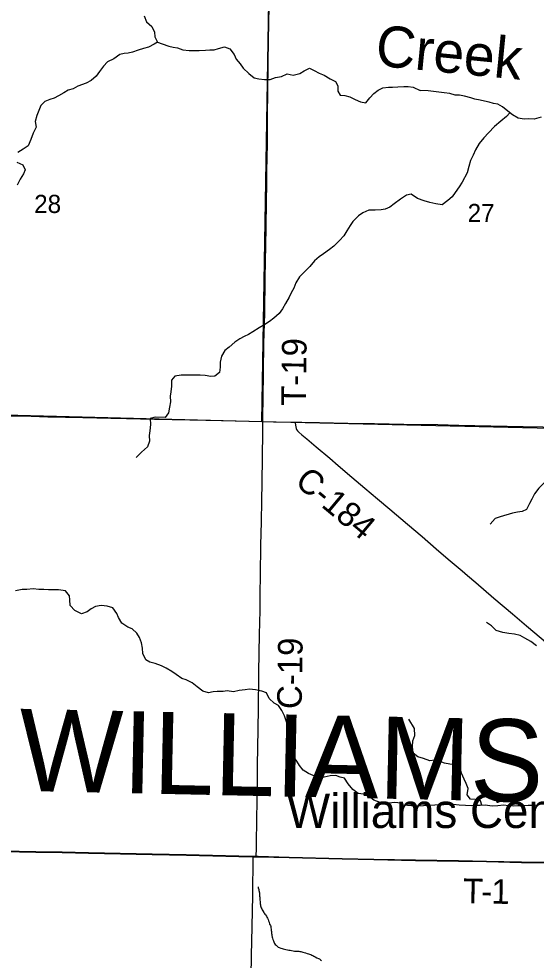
# Model space of a CAD drawing. Extents: x 0 to 34, y 0 to 22.
# Drawn here: x 3.097 to 4.291, y 16.256 to 18.428 of the extents above; entities that cross this region are included whole.
import ezdxf

# ---------------------------------------------------------------- set-up
doc = ezdxf.new("R2010")
doc.units = 0
for name, color, linetype in [('GM_X_County_Road', 7, 'Continuous'), ('GM_X_County_Road_Text', 7, 'Continuous'), ('GM_X_County_Text', 7, 'Continuous'), ('GM_X_Minor_River', 7, 'Continuous'), ('GM_X_Minor_River_Text', 7, 'Continuous'), ('GM_X_Section', 7, 'Continuous'), ('GM_X_Section_Text', 7, 'Continuous'), ('GM_X_Township_Road', 7, 'Continuous'), ('GM_X_Township_Road_Text', 7, 'Continuous'), ('GM_X_Unincorporated_Text', 7, 'Continuous'), ('GM_X_US_Route', 7, 'Continuous'), ('SH_Cut_Line', 7, 'Continuous')]:
    doc.layers.add(name, color=color, linetype=linetype)

msp = doc.modelspace()

# ---------------------------------------------------------------- linework, layer by layer
at = {"layer": 'GM_X_County_Road'}
msp.add_line((3.6378, 16.4946), (3.6451, 16.4944), dxfattribs=at)
for points in [[(3.6601, 17.499), (3.6602, 17.5105), (3.6605, 17.5528), (3.6615, 17.6119), (3.6626, 17.6796), (3.6643, 17.748), (3.6655, 17.8307), (3.6667, 17.9059), (3.6674, 17.9469), (3.6685, 18.0066), (3.669, 18.0464), (3.6695, 18.0806), (3.6699, 18.1042), (3.6705, 18.1427), (3.6711, 18.1831), (3.6712, 18.2148), (3.6714, 18.249), (3.6717, 18.2701), (3.6722, 18.3105), (3.6727, 18.3397), (3.6735, 18.3901), (3.6741, 18.4261), (3.6746, 18.4498)], [(3.6451, 16.4944), (3.6449, 16.4976), (3.6449, 16.5014), (3.6451, 16.5082), (3.6453, 16.5281), (3.6468, 16.6263), (3.6475, 16.6691), (3.648, 16.7015), (3.6486, 16.7512), (3.6489, 16.7841), (3.6499, 16.8419), (3.6503, 16.8655), (3.6505, 16.8836), (3.6509, 16.9184), (3.6518, 16.9668), (3.6525, 17.006), (3.6531, 17.0364), (3.6536, 17.0613), (3.6542, 17.1011), (3.6549, 17.144), (3.6558, 17.2136), (3.6568, 17.267), (3.6576, 17.3167), (3.6582, 17.3571), (3.6601, 17.4752), (3.6601, 17.499)], [(3.7344, 17.4974), (3.7347, 17.4953), (3.7359, 17.4864), (3.7368, 17.4826), (3.7379, 17.4802), (3.7397, 17.4776), (3.7432, 17.4739), (3.7504, 17.4678), (3.7615, 17.4587), (3.7828, 17.4406), (3.8148, 17.4139), (3.8341, 17.3973), (3.8654, 17.3708), (3.8953, 17.3454), (3.9249, 17.3208), (3.9532, 17.2965), (3.9939, 17.2618), (4.0275, 17.2332), (4.0601, 17.2053), (4.088, 17.1815), (4.1202, 17.1541), (4.1324, 17.1436), (4.1518, 17.127), (4.1934, 17.0915), (4.2364, 17.0547), (4.2685, 17.0272), (4.2876, 17.0113), (4.3472, 16.9614)], [(2.6448, 16.5144), (2.8005, 16.5116), (2.9068, 16.5095), (2.9572, 16.5086), (3.0604, 16.5067), (3.1362, 16.5053), (3.1971, 16.5041), (3.2581, 16.5028), (3.4047, 16.4997), (3.4837, 16.498), (3.6049, 16.4953), (3.6286, 16.4947), (3.6378, 16.4946)]]:
    msp.add_lwpolyline(points, dxfattribs=at)
at = {"layer": 'GM_X_County_Text'}
for points in [[(3.0601, 16.5072), (3.136, 16.5059), (3.1969, 16.5047), (3.2578, 16.5034), (3.4045, 16.5002), (3.4834, 16.4986), (3.6047, 16.4958), (3.6284, 16.4952), (3.6376, 16.4952), (3.6449, 16.495), (3.6492, 16.4949), (3.721, 16.493), (3.8428, 16.49), (3.9161, 16.4884), (4.0125, 16.4864), (4.1113, 16.4848), (4.1766, 16.4837), (4.2567, 16.4818), (4.3239, 16.4808)], [(4.3239, 16.4808), (4.2567, 16.4818), (4.1766, 16.4837), (4.1113, 16.4848), (4.0125, 16.4864), (3.9161, 16.4884), (3.8428, 16.49), (3.721, 16.493), (3.6492, 16.4949), (3.6449, 16.495), (3.6376, 16.4952), (3.6284, 16.4952), (3.6047, 16.4958), (3.4834, 16.4986), (3.4045, 16.5002), (3.2578, 16.5034), (3.1969, 16.5047), (3.136, 16.5059), (3.0601, 16.5072)]]:
    msp.add_lwpolyline(points, dxfattribs=at)
at = {"layer": 'GM_X_Minor_River'}
for points in [[(3.3862, 18.4354), (3.3919, 18.4216), (3.4042, 18.4103), (3.4103, 18.3972), (3.4108, 18.3866), (3.4173, 18.3746), (3.4274, 18.3702), (3.4432, 18.3652), (3.4531, 18.3631), (3.4633, 18.3613), (3.4753, 18.3564), (3.4897, 18.3549), (3.5018, 18.355), (3.5128, 18.3547), (3.5276, 18.3558), (3.5379, 18.3563), (3.5474, 18.3568), (3.5577, 18.3596), (3.5715, 18.3634), (3.5839, 18.3589), (3.5938, 18.3458), (3.5988, 18.335), (3.608, 18.3241), (3.615, 18.3141), (3.6276, 18.302), (3.6399, 18.2918), (3.6508, 18.2896), (3.6637, 18.2882), (3.6766, 18.2882), (3.6896, 18.2928), (3.7029, 18.2951), (3.716, 18.3009), (3.73, 18.2982), (3.7456, 18.302), (3.7553, 18.3078), (3.7676, 18.3143), (3.7788, 18.3087), (3.7897, 18.3031), (3.8017, 18.2979), (3.8155, 18.2899), (3.8275, 18.2836), (3.8329, 18.2735), (3.833, 18.2614), (3.8388, 18.2518), (3.8494, 18.2511), (3.8607, 18.2478), (3.8731, 18.2418), (3.8851, 18.2365), (3.8976, 18.2343), (3.9066, 18.2458), (3.916, 18.2555), (3.9264, 18.2632), (3.9368, 18.2693), (3.9501, 18.2701), (3.9596, 18.2707), (3.9718, 18.2711), (3.9851, 18.2719), (3.9953, 18.272), (4.0071, 18.2702), (4.0228, 18.2628)], [(3.4173, 18.3746), (3.4092, 18.3695), (3.3961, 18.363), (3.385, 18.3599), (3.372, 18.3557), (3.359, 18.3511), (3.3495, 18.3491), (3.34, 18.3482), (3.3297, 18.3461), (3.3161, 18.3359), (3.3019, 18.3286), (3.2922, 18.319), (3.2831, 18.3064), (3.2752, 18.2959), (3.264, 18.2856), (3.2521, 18.2794), (3.2329, 18.2731), (3.2221, 18.2669), (3.2107, 18.2638), (3.2006, 18.2576), (3.1883, 18.2503), (3.1783, 18.2453), (3.1684, 18.2418), (3.1569, 18.2375), (3.1475, 18.2279), (3.1434, 18.217), (3.1382, 18.205), (3.1348, 18.1914), (3.1371, 18.178), (3.1303, 18.1642), (3.1243, 18.1499), (3.1186, 18.1352), (3.107, 18.1272), (3.095, 18.1199)], [(4.1715, 18.2381), (4.1617, 18.2406), (4.1496, 18.2431), (4.1398, 18.2456), (4.1254, 18.25), (4.1141, 18.2518), (4.1039, 18.2523), (4.0918, 18.2556), (4.0786, 18.2574), (4.0664, 18.2587), (4.0536, 18.2601), (4.0415, 18.2619), (4.0228, 18.2628)], [(4.3023, 18.2011), (4.2859, 18.1968), (4.2727, 18.1971), (4.2632, 18.1969), (4.2496, 18.1991), (4.2361, 18.2069), (4.2252, 18.2151), (4.2129, 18.2248), (4.202, 18.2311), (4.1922, 18.2328), (4.182, 18.2356), (4.1715, 18.2381)], [(4.2303, 18.2113), (4.2227, 18.2026), (4.2093, 18.1923), (4.195, 18.1796), (4.181, 18.1647), (4.1698, 18.1539), (4.1593, 18.1401), (4.1511, 18.1258), (4.1452, 18.1138), (4.1392, 18.101), (4.1356, 18.0875), (4.1315, 18.0727), (4.1201, 18.051), (4.1134, 18.0401), (4.1041, 18.0274), (4.0967, 18.0176), (4.0867, 18.0091), (4.0736, 17.9991), (4.0592, 18.0009), (4.0452, 18.0046), (4.0324, 18.0083), (4.0169, 18.0137)], [(3.0926, 18.0972), (3.1061, 18.0912), (3.1119, 18.08), (3.1078, 18.0702), (3.0999, 18.0579), (3.0931, 18.044)], [(4.0169, 18.0137), (4.0027, 18.0232), (3.9916, 18.0216), (3.9781, 18.0117), (3.9634, 18.0011), (3.9529, 17.9934), (3.9426, 17.9891), (3.933, 17.9874), (3.9194, 17.9866), (3.9049, 17.9863), (3.8911, 17.9805), (3.8811, 17.9736), (3.8678, 17.9606), (3.8619, 17.9509), (3.854, 17.9386), (3.8473, 17.927), (3.8371, 17.9163), (3.8239, 17.9033), (3.8142, 17.8956), (3.7999, 17.8857), (3.7899, 17.8792), (3.7794, 17.8699), (3.7688, 17.8569), (3.7563, 17.8444), (3.7447, 17.8329), (3.7363, 17.8187), (3.7318, 17.8067), (3.7251, 17.7955), (3.7211, 17.7857), (3.7127, 17.7715), (3.7056, 17.7592), (3.6977, 17.7484), (3.6857, 17.7373), (3.6756, 17.7296), (3.6648, 17.7226), (3.6517, 17.715), (3.637, 17.7055), (3.627, 17.6997), (3.6167, 17.695), (3.6067, 17.6896), (3.5955, 17.6823), (3.5823, 17.6701), (3.5726, 17.6624), (3.5643, 17.6494), (3.5617, 17.6361), (3.5614, 17.6244), (3.5603, 17.6119), (3.5494, 17.6035), (3.5399, 17.6026), (3.5267, 17.6048), (3.5157, 17.6055), (3.5013, 17.6055), (3.4907, 17.6057), (3.4812, 17.6056), (3.4713, 17.6055), (3.4568, 17.6039), (3.449, 17.5943), (3.449, 17.5806), (3.4476, 17.5674), (3.4462, 17.5576), (3.4466, 17.5446), (3.4448, 17.5318), (3.4425, 17.519), (3.4343, 17.5085), (3.4112, 17.5091), (3.4004, 17.5056), (3.4005, 17.4923), (3.3993, 17.4776), (3.3979, 17.4666), (3.3984, 17.4537), (3.3942, 17.4401), (3.3802, 17.428), (3.3678, 17.4158)], [(4.3439, 17.3705), (4.334, 17.3688), (4.3238, 17.3671), (4.3103, 17.3578), (4.2968, 17.3452), (4.2867, 17.3321), (4.2808, 17.3194), (4.2753, 17.3096), (4.2682, 17.2961), (4.2582, 17.2914), (4.248, 17.2897), (4.2365, 17.2872), (4.2076, 17.2787), (4.1961, 17.2747), (4.1848, 17.2617)], [(3.9839, 16.6138), (3.9782, 16.6178), (3.965, 16.62), (3.9444, 16.6175), (3.9308, 16.6197), (3.9165, 16.6247), (3.9065, 16.6329), (3.8922, 16.6386), (3.8797, 16.6404), (3.8678, 16.6498), (3.8571, 16.6626), (3.8487, 16.6757), (3.8389, 16.6783), (3.8288, 16.6816), (3.8151, 16.6808), (3.8014, 16.6781), (3.7899, 16.6769), (3.776, 16.6818), (3.7651, 16.6866), (3.7532, 16.6945), (3.7444, 16.7054), (3.7385, 16.715), (3.729, 16.7278), (3.724, 16.7408), (3.7247, 16.7529), (3.7262, 16.7658), (3.7238, 16.7753), (3.7185, 16.7929), (3.7147, 16.8059), (3.7101, 16.8193), (3.7039, 16.8316), (3.6959, 16.8432), (3.6862, 16.8488), (3.6747, 16.8597), (3.6682, 16.8724), (3.6577, 16.8768), (3.6433, 16.8795), (3.6293, 16.881), (3.6194, 16.8797), (3.6057, 16.8778), (3.5927, 16.8747), (3.578, 16.8777), (3.5684, 16.8761), (3.5548, 16.8757), (3.5453, 16.8748), (3.5346, 16.8728), (3.5214, 16.8765), (3.5087, 16.8864), (3.4969, 16.8961), (3.483, 16.9026), (3.4732, 16.9059), (3.4598, 16.9149), (3.4497, 16.9216), (3.4366, 16.9296), (3.4261, 16.9352), (3.4118, 16.9405), (3.3994, 16.9438), (3.3897, 16.9486), (3.3832, 16.9632), (3.382, 16.9757), (3.3797, 16.9883), (3.3758, 17.0006), (3.3696, 17.0102), (3.3585, 17.0204), (3.3483, 17.0244), (3.3345, 17.0335), (3.3272, 17.0462), (3.3229, 17.0558), (3.3138, 17.0686), (3.301, 17.0727), (3.287, 17.0742), (3.274, 17.0722), (3.264, 17.0668), (3.2543, 17.0595), (3.2417, 17.0549), (3.226, 17.0629), (3.2152, 17.0741), (3.2148, 17.0874), (3.2139, 17.0969), (3.2043, 17.1078), (3.1888, 17.1105), (3.1748, 17.1105), (3.1653, 17.1107), (3.1547, 17.1114), (3.1433, 17.1113), (3.1297, 17.1124), (3.1152, 17.1112), (3.1046, 17.1111), (3.0894, 17.1081)], [(4.2917, 16.981), (4.2786, 16.9914), (4.2647, 16.9985), (4.2538, 17.0052), (4.241, 17.0081), (4.2281, 17.0099), (4.2142, 17.0117), (4.1987, 17.0165), (4.1875, 17.0273), (4.1759, 17.0348)], [(4.1653, 16.6131), (4.1623, 16.6232), (4.1498, 16.6265), (4.1392, 16.6275), (4.1315, 16.6375), (4.134, 16.6518), (4.1293, 16.6633), (4.125, 16.6736), (4.1188, 16.687), (4.1152, 16.7004), (4.1051, 16.7062), (4.0919, 16.708), (4.0794, 16.7105), (4.0692, 16.7141), (4.0572, 16.717), (4.0454, 16.7161), (4.0307, 16.721), (4.0179, 16.7254), (4.0071, 16.7335), (4.0051, 16.7488), (4.0061, 16.762), (4.0109, 16.7744), (4.0102, 16.7901), (3.9969, 16.8121)], [(4.296, 16.6134), (4.2827, 16.6129), (4.2724, 16.6124), (4.2588, 16.6123), (4.2482, 16.6117), (4.2379, 16.6111), (4.2273, 16.6117), (4.2156, 16.6135), (4.2027, 16.6118), (4.189, 16.6113), (4.1731, 16.6132), (4.1613, 16.613), (4.1511, 16.6124), (4.1408, 16.6123), (4.128, 16.6129), (4.1132, 16.6136), (4.0999, 16.6149), (4.0905, 16.6148), (4.0779, 16.6146), (4.0677, 16.6141), (4.0571, 16.6131), (4.0445, 16.613), (4.0172, 16.6112), (4.0028, 16.6123), (3.9839, 16.6138)], [(3.6489, 16.4249), (3.6492, 16.4245), (3.6496, 16.4226), (3.6507, 16.4188), (3.6511, 16.4169), (3.6521, 16.4108), (3.6521, 16.4085), (3.6525, 16.4058), (3.6525, 16.4035), (3.6528, 16.4009), (3.6532, 16.3982), (3.6535, 16.394), (3.6539, 16.391), (3.6538, 16.3883), (3.6538, 16.3857), (3.6545, 16.3834), (3.6549, 16.3815), (3.6553, 16.3788), (3.6564, 16.3765), (3.6575, 16.3742), (3.6586, 16.3719), (3.6597, 16.3693), (3.6624, 16.3658), (3.6631, 16.3639), (3.6646, 16.362), (3.6661, 16.3601), (3.6684, 16.357), (3.6695, 16.3547), (3.6706, 16.3524), (3.6721, 16.3497), (3.6732, 16.3467), (3.6747, 16.3433), (3.6758, 16.3391), (3.6777, 16.336), (3.6784, 16.3333), (3.6788, 16.3307), (3.6791, 16.3276), (3.6795, 16.3246), (3.6798, 16.3219), (3.6798, 16.32), (3.6802, 16.317), (3.6805, 16.3147), (3.6809, 16.3124), (3.6816, 16.309), (3.6823, 16.3063), (3.6835, 16.3036), (3.6846, 16.3002), (3.6857, 16.2979), (3.6864, 16.296), (3.6872, 16.2941), (3.6887, 16.2918), (3.6906, 16.2903), (3.6958, 16.286), (3.6981, 16.2852), (3.7019, 16.2837), (3.7046, 16.2829), (3.7072, 16.2817), (3.7099, 16.2809), (3.7133, 16.2805), (3.7167, 16.2797), (3.7201, 16.2789), (3.7235, 16.2785), (3.7262, 16.2781), (3.7304, 16.2773), (3.7334, 16.2769), (3.7357, 16.2765), (3.7383, 16.2764), (3.7414, 16.2764), (3.7433, 16.2764), (3.7452, 16.276), (3.7475, 16.2756), (3.7497, 16.2748), (3.7524, 16.274), (3.7554, 16.2732), (3.7585, 16.2724), (3.7623, 16.2713), (3.7653, 16.2705), (3.768, 16.2697), (3.7706, 16.2685), (3.7729, 16.2677), (3.7751, 16.2666), (3.7778, 16.265), (3.7808, 16.2635), (3.785, 16.2615), (3.7884, 16.26), (3.7907, 16.2588), (3.7933, 16.2569), (3.7956, 16.2553)]]:
    msp.add_lwpolyline(points, dxfattribs=at)
at = {"layer": 'GM_X_Section'}
for points in [[(2.687, 18.5293), (3.6746, 18.5151), (3.6575, 17.498), (2.649, 17.5241), (2.6545, 17.8761)], [(3.6746, 18.5151), (4.6642, 18.4797), (4.6605, 17.4748), (3.6575, 17.498)]]:
    msp.add_lwpolyline(points, close=True, dxfattribs=at)
at = {"layer": 'GM_X_Township_Road'}
msp.add_line((3.6378, 16.4946), (3.6451, 16.4944), dxfattribs=at)
for points in [[(3.6601, 17.499), (3.6602, 17.5105), (3.6605, 17.5528), (3.6615, 17.6119), (3.6626, 17.6796), (3.6643, 17.748), (3.6655, 17.8307), (3.6667, 17.9059), (3.6674, 17.9469), (3.6685, 18.0066), (3.669, 18.0464), (3.6695, 18.0806), (3.6699, 18.1042), (3.6705, 18.1427), (3.6711, 18.1831), (3.6712, 18.2148), (3.6714, 18.249), (3.6717, 18.2701), (3.6722, 18.3105), (3.6727, 18.3397), (3.6735, 18.3901), (3.6741, 18.4261), (3.6746, 18.4498)], [(2.6448, 16.5144), (2.8005, 16.5116), (2.9068, 16.5095), (2.9572, 16.5086), (3.0604, 16.5067), (3.1362, 16.5053), (3.1971, 16.5041), (3.2581, 16.5028), (3.4047, 16.4997), (3.4837, 16.498), (3.6049, 16.4953), (3.6286, 16.4947), (3.6378, 16.4946)], [(3.6247, 15.4985), (3.625, 15.5238), (3.6252, 15.5481), (3.6255, 15.5835), (3.6255, 15.6108), (3.6264, 15.6842), (3.6271, 15.7414), (3.6275, 15.7749), (3.628, 15.8352), (3.6286, 15.8725), (3.6293, 15.9303), (3.6308, 16.0527), (3.6321, 16.1615), (3.6331, 16.2162), (3.6341, 16.2684), (3.6346, 16.2982), (3.6366, 16.4047), (3.6378, 16.4946)], [(3.6451, 16.4944), (3.6494, 16.4943), (3.7212, 16.4924), (3.843, 16.4895), (3.9164, 16.4879), (4.0127, 16.4859), (4.1115, 16.4842), (4.1768, 16.4831), (4.257, 16.4812), (4.3241, 16.4802), (4.408, 16.4784), (4.4441, 16.4778), (4.5199, 16.4765), (4.5671, 16.4758), (4.5702, 16.4758)]]:
    msp.add_lwpolyline(points, dxfattribs=at)
at = {"layer": 'GM_X_US_Route'}
msp.add_lwpolyline([(3.0766, 17.5122), (3.1257, 17.511), (3.1636, 17.51), (3.245, 17.5082), (3.309, 17.5067), (3.3457, 17.5058), (3.4097, 17.5046), (3.4912, 17.5027), (3.5645, 17.501), (3.6601, 17.499), (3.6844, 17.4985), (3.7344, 17.4974), (3.7497, 17.4971), (3.7907, 17.4966), (3.856, 17.4952), (3.9176, 17.4941), (3.9853, 17.4927), (4.0636, 17.4916), (4.1121, 17.4904), (4.2607, 17.4876), (4.3962, 17.4853)], dxfattribs=at)
at = {"layer": 'SH_Cut_Line'}
for points in [[(4.3239, 16.4808), (4.2567, 16.4818), (4.1766, 16.4837), (4.1113, 16.4848), (4.0125, 16.4864), (3.9161, 16.4884), (3.8428, 16.49), (3.721, 16.493), (3.6492, 16.4949), (3.6449, 16.495), (3.6376, 16.4952), (3.6284, 16.4952), (3.6047, 16.4958), (3.4834, 16.4986), (3.4045, 16.5002), (3.2578, 16.5034), (3.1969, 16.5047), (3.136, 16.5059), (3.0601, 16.5072)], [(3.0601, 16.5072), (3.136, 16.5059), (3.1969, 16.5047), (3.2578, 16.5034), (3.4045, 16.5002), (3.4834, 16.4986), (3.6047, 16.4958), (3.6284, 16.4952), (3.6376, 16.4952), (3.6449, 16.495), (3.6492, 16.4949), (3.721, 16.493), (3.8428, 16.49), (3.9161, 16.4884), (4.0125, 16.4864), (4.1113, 16.4848), (4.1766, 16.4837), (4.2567, 16.4818), (4.3239, 16.4808)]]:
    msp.add_lwpolyline(points, dxfattribs=at)

# ---------------------------------------------------------------- texts
at = {"layer": 'GM_X_County_Road_Text'}
for s, rotation, p in [('C-184', 319.9871, (3.7312, 17.3554)), ('C-19', 89.1256, (3.7496, 16.835))]:
    msp.add_text(s, height=0.05682, rotation=rotation, dxfattribs=at).set_placement(p)
at = {"layer": 'GM_X_County_Text'}
msp.add_text('WILLIAMS COUNTY', height=0.189394, rotation=358.7748, dxfattribs=at).set_placement((3.0959, 16.6466))
at = {"layer": 'GM_X_Minor_River_Text'}
msp.add_text('Creek', height=0.09475, rotation=354.3861, dxfattribs=at).set_placement((3.9175, 18.3205))
at = {"layer": 'GM_X_Section_Text'}
for s, p in [('28', (3.1323, 17.9801)), ('27', (4.1327, 17.9592))]:
    msp.add_text(s, height=0.04186, rotation=0, dxfattribs=at).set_placement(p)
at = {"layer": 'GM_X_Township_Road_Text'}
for s, height, rotation, p in [('T-19', 0.05682, 89.2902, (3.7593, 17.5348)), ('T', 0.0568, 358.804, (4.1214, 16.3876)), ('1', 0.0568, 358.8213, (4.1869, 16.3863)), ('-', 0.0568, 358.8107, (4.1638, 16.3867))]:
    msp.add_text(s, height=height, rotation=rotation, dxfattribs=at).set_placement(p)
at = {"layer": 'GM_X_Unincorporated_Text'}
msp.add_text('Williams Center', height=0.078977, rotation=0, dxfattribs=at).set_placement((3.7157, 16.5608))

doc.saveas('drawing.dxf')
